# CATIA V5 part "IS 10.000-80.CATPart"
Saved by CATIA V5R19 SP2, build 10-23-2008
Part number: IS 10.000-80
Bounding box of the stored display mesh (mm): x -97.324 to 97.324, y -97.5 to 97.5, z 0 to 320
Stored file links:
  C:\Users\Bora\Desktop\3D Katı model\IS serisi\IS 10.000\IS 10.000-80.CATPart
  C:\Program Files\Dassault Systemes\B19\intel_a\reffiles\standard\MetricThickPitch.txt
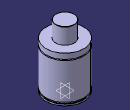
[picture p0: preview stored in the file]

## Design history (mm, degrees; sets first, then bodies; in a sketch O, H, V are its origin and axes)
Body1 (main body)
  Sketch1 on yz-plane, origin (0, 0, 0), H (0, 1, 0), V (0, 0, 1)
    point P1 (97.5, 209)
    point P4 (97.5, 204)
    point P7 (47.5, 319)
    point P9 (47.5, 319)
    point P13 (97.5, 209)
    point P14 (97.5, 204)
    line L1 (97.5, 209) -> (97.5, 237)
    line L2 (97.5, 16) -> (97.5, 204)
    line L3 (93.5, 16) -> (93.5, 8)
    arc A1 centre (46.5, 319) radius 1 from (47.5, 319) to (46.5, 320) ccw
    line L4 (47.5, 319) -> (47.5, 237)
    line L5 (97.5, 0) -> (97.5, 8)
    arc A2 centre (97.5, 206.5) radius 2.5 from (97.5, 209) to (97.5, 204) ccw
    line L6 (46.5, 320) -> (0, 320)
    line L7 (47.5, 237) -> (97.5, 237)
    line L8 (93.5, 16) -> (97.5, 16)
    line L9 (97.5, 8) -> (93.5, 8)
    line L10 (97.5, 0) -> (0, 0)
    tangency: L6 A1
    horizontal: L7 H, L8 H, L9 H, L10 H
    coincidence: P1 P13, P4 P14, P7 P9
  Shaft1: profile Sketch1, axis Sketch1.V, angle 360
  Sketch2 on face of Shaft1 from Sketch1.L10, origin (0, 0, 0), H (1, 0, 0), V (0, -1, 0)
    point P1 (60, 0)
    distance P1 V = 60
  Hole1: placed by Sketch2, at (60, 0, 0) direction (0, 0, 1), diameter 10.106, depth 16, threaded "M12", thread diameter 12, thread depth 16, pitch 1.75
  CircPattern1: of Hole1, instances 4, angular step 90, axis from xy-plane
